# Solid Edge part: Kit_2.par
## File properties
Sűrűség: 0,000 kg/m^3
Pontosság: 0,990
Author: ahadarics
Last saved by: psaghy
Revision: 78
Username: ahadarics
Dokumentum tartalom típus: 0
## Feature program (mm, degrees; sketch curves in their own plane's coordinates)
base feature "unnamed BaseFeature 1"
sketch for "Furat_1" plane through (0, 0, 41.5) normal (0, 0, 1) x-axis (-0.707107, -0.707107, 0)
  hole centre (-39.9515, 0) bore radius 3.3235
hole "Furat_1" nominal diameter 8 finite  VBottomAngle = 118 deg; ThreadDepth = 16 mm
sketch for "unnamed Hole 1" plane through (0, 0, 41.5) normal (0, 0, 1) x-axis (-0.707107, -0.707107, 0)
  hole centre (0, -39.9515) bore radius 3.3235
hole "unnamed Hole 1" finite
sketch for "unnamed Hole 2" plane through (0, 0, 41.5) normal (0, 0, 1) x-axis (-0.707107, -0.707107, 0)
  hole centre (39.9515, 0) bore radius 3.3235
hole "unnamed Hole 2" finite
sketch for "unnamed Hole 3" plane through (0, 0, 41.5) normal (0, 0, 1) x-axis (-0.707107, -0.707107, 0)
  hole centre (0, 39.9515) bore radius 3.3235
hole "unnamed Hole 3" finite
pattern "unnamed Pattern 1" of "Furat_1", "unnamed Hole 1", "unnamed Hole 2", "unnamed Hole 3"
sketch for "Furat_5" plane through (37.5, 0.0062, 22.7488) normal (1, 0, 0) x-axis (0, 0, -1)
hole "Furat_5" diameter 16.662 finite  ThreadDepth = 17 mm
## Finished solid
Body 1: solid body, 521 faces, 1211 edges, 754 vertices, 8 internal voids.
  Faces by surface: cylinder 204, plane 147, cone 54, torus 48, sphere 37, spline 27, swept 4
  Edges by curve: curve on surface 471, circle 397, line 331, spline 12
Bounding box of the edges (mm; curved faces can reach further): 75.001 x 75.000 x 59.500, from (-37.5, -37.5, 8) to (37.5009, 37.5, 67.5).
Cylindrical faces by radius (mm): R0.3049 x1, R0.3063 x2, R0.3073 x1, R0.3094 x1, R0.3138 x1, R0.3275 x1, R0.3358 x1, R0.3579 x2, R0.3595 x2, R0.3746 x2, R0.3825 x2, R0.3862 x2, R0.3932 x1, R0.395 x1, R0.3966 x1, R0.3998 x2, R0.4022 x1, R0.4063 x1, R0.4065 x1, R0.4073 x2, R0.4133 x1, R0.4335 x2, R0.4417 x1, R0.4627 x2, R0.4813 x1, R0.4994 x1, R0.5 x3, R0.5003 x1, R0.5051 x1, R0.5233 x1, R0.5325 x1, R0.5327 x1, R0.5437 x2, R0.5682 x1, R0.5785 x2, R0.6044 x1, R0.6048 x2, R0.6079 x1, R0.6085 x1, R0.6126 x1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
Conical faces (half-angle, radius in mm at the cone's reference point): 1 deg R23.75 x4, 1 deg R28 x4, 1.6538 deg R11.75 x1, 3.5477 deg R12.7454 x1, 5.762 deg R10.4 x1, 11.1239 deg R10.0056 x1, 15 deg R20.3906 x1, 15.3654 deg R10.7214 x1, 19.3654 deg R11.1921 x1, 25.0169 deg R14.31 x1, 30 deg R5.1443 x1, 30 deg R11.8557 x2, 30 deg R12.1443 x1, 30 deg R21.75 x1, 32.8285 deg R32.5 x1, 37.7468 deg R27.2199 x3, 37.7468 deg R33.5 x3, 45 deg R2.75 x1, 45 deg R2.825 x1, 45 deg R4.3 x8, 45 deg R6.35 x8, 45 deg R7.47 x1, 45 deg R10.15 x2, 45 deg R15.25 x1, 59 deg R3.3235 x4
Toroidal faces (ring radius, tube radius in mm): R0.5012 r0.5005 x1, R1 r0.5 x1, R1.0357 r0.4999 x1, R4.3 r0.3 x4, R4.7 r0.3 x1, R6.45 r0.2 x4, R7.15 r0.5 x4, R10.25 r1 x2, R10.3 r0.3 x1, R10.3085 r0.3 x1, R11.4279 r0.25 x1, R12 r0.5 x1, R12.2464 r0.5 x1, R14.8 r0.2 x1, R19 r2 x1, R19.3663 r0.5 x1, R23 r0.5 x1, R24.6454 r1 x1, R24.7327 r1 x3, R25.9494 r1 x3, R27.0059 r1 x3, R27.0694 r1 x1, R34 r1 x3, R38.0449 r1 x1, R38.5 r1 x6
Spherical faces by radius (mm): R1 x37
Planar faces by outward normal: +x 22, +y 8, +z 31, -x 2, -y 7, -z 19, oblique 58
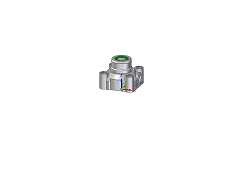
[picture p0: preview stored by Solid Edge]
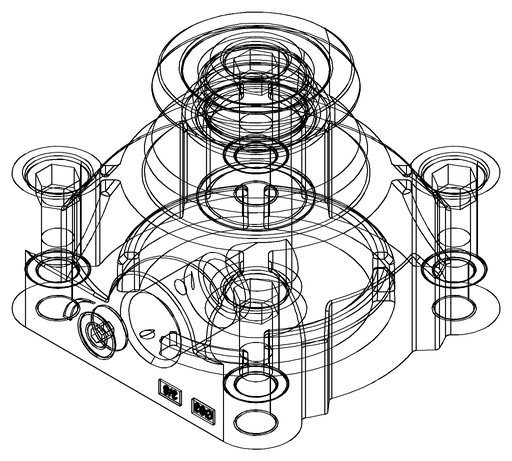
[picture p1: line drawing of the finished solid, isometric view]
